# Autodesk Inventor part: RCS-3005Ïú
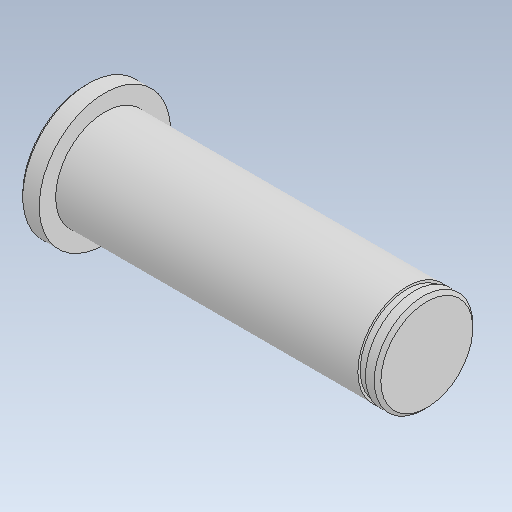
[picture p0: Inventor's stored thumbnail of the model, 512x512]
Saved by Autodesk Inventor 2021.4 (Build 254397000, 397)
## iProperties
Created: 2019-12
Part Number: RCS-3005Ïú
Material: Ogólny
Document SubType Name: Modeling
Designer: user
Density: 1 g/cm^3
Appearance: Domyślna
Author: user
Revision Number: ÈÎºÎ
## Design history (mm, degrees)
feature "1"
node "Bryła1"
